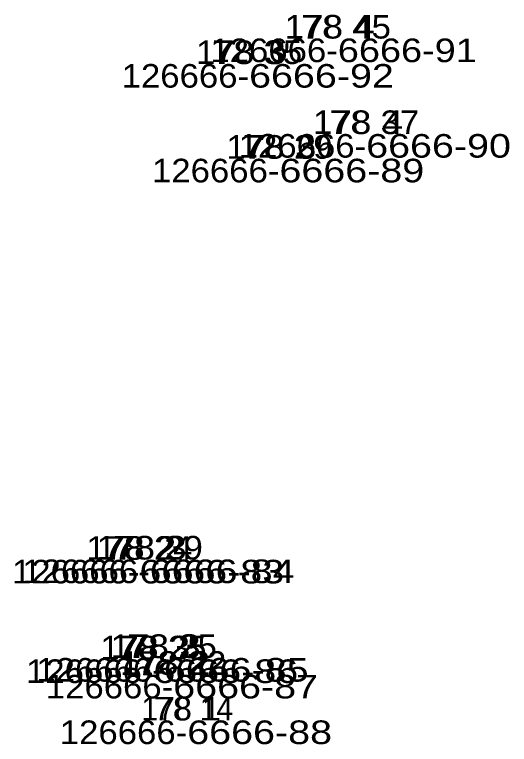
# Model space of a CAD drawing. Extents: x -598473 to -594209, y -1163589 to -1162143.
# Drawn here: x -594738.72 to -594707.27, y -1162558.44 to -1162512.05 of the extents above; entities that cross this region are included whole.
import ezdxf
from ezdxf.enums import TextEntityAlignment as Align

# ---------------------------------------------------------------- set-up
doc = ezdxf.new("R2010")
doc.units = 0
doc.header["$LTSCALE"] = 0.6
for name, color, linetype in [('57', 7, 'Continuous'), ('58', 7, 'Continuous'), ('61', 7, 'Continuous'), ('62', 7, 'Continuous')]:
    doc.layers.add(name, color=color, linetype=linetype)

msp = doc.modelspace()

# ---------------------------------------------------------------- texts
at = {"layer": '57'}
for s, width, p in [('78 4', 1.2, (-594718.178, -1162513.577)), ('78 3', 1.2, (-594723.818, -1162515.197)), ('78 4', 1.2, (-594716.378, -1162519.647)), ('78 3', 1.2, (-594721.888, -1162521.217)), ('78 2', 1.2, (-594730.788, -1162546.707)), ('78 3', 1.2, (-594730.128, -1162546.687)), ('78 3', 1.2, (-594729.898, -1162553.037)), ('78 3', 1.2, (-594729.238, -1162552.947)), ('78 2', 1.2, (-594728.638, -1162554.017)), ('78 1', 1.1, (-594727.7485, -1162556.917))]:
    msp.add_text(s, height=1.5, dxfattribs=dict(at, width=width)).set_placement(p, align=Align.CENTER)
at = {"layer": '58'}
for s, width, p in [('178 45', 1.1, (-594718.1785, -1162513.577)), ('178 35', 1.1, (-594723.8185, -1162515.197)), ('178 37', 1.1, (-594716.3785, -1162519.647)), ('178 29', 1.1, (-594721.888, -1162521.217)), ('178 24', 1.1, (-594730.7885, -1162546.707)), ('178 29', 1.1, (-594730.128, -1162546.687)), ('178 25', 1.1, (-594729.8985, -1162553.037)), ('178 25', 1.1, (-594729.2385, -1162552.947)), ('178 22', 1.1, (-594728.6385, -1162554.017)), ('178 14', 0.95, (-594727.7475, -1162556.917))]:
    msp.add_text(s, height=1.5, dxfattribs=dict(at, width=width)).set_placement(p, align=Align.CENTER)
at = {"layer": '61', "width": 1.1}
for p in [(-594718.178, -1162515.077), (-594723.818, -1162516.697), (-594716.378, -1162521.147), (-594721.888, -1162522.717), (-594730.788, -1162548.207), (-594730.128, -1162548.187), (-594729.898, -1162554.537), (-594729.238, -1162554.447), (-594728.638, -1162555.517), (-594727.748, -1162558.417)]:
    msp.add_text('126666-', height=1.5, dxfattribs=at).set_placement(p, align=Align.RIGHT)
at = {"layer": '62'}
for s, width, p in [('6666-91', 1.2, (-594718.178, -1162515.077)), ('6666-92', 1.25, (-594723.818, -1162516.697)), ('6666-90', 1.25, (-594716.378, -1162521.147)), ('6666-89', 1.25, (-594721.888, -1162522.717)), ('6666-83', 1.25, (-594730.788, -1162548.207)), ('6666-84', 1.25, (-594730.128, -1162548.187)), ('6666-86', 1.25, (-594729.898, -1162554.537)), ('6666-85', 1.25, (-594729.238, -1162554.447)), ('6666-87', 1.25, (-594728.638, -1162555.517)), ('6666-88', 1.25, (-594727.748, -1162558.417))]:
    msp.add_text(s, height=1.5, dxfattribs=dict(at, width=width)).set_placement(p)

doc.saveas('drawing.dxf')
